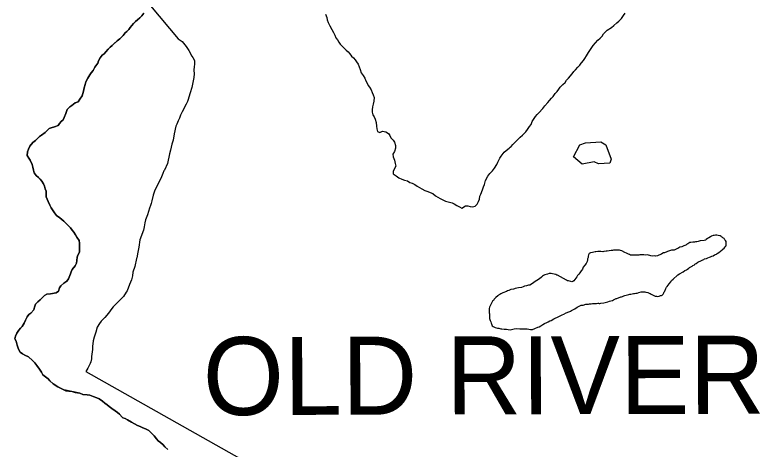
# Model space of a CAD drawing. Extents: x 3180038 to 3217926, y 922069 to 947485.
# Drawn here: x 3193100 to 3194055, y 938575 to 939132 of the extents above; entities that cross this region are included whole.
import ezdxf

# ---------------------------------------------------------------- set-up
doc = ezdxf.new("R2010")
doc.units = 0
for name, color, linetype in [('V-RIVR-IDEN', 7, 'Continuous'), ('V-SITE-VEGE', 7, 'Continuous'), ('V-TOPO-SHOR', 7, 'Continuous')]:
    doc.layers.add(name, color=color, linetype=linetype)

msp = doc.modelspace()

# ---------------------------------------------------------------- linework, layer by layer
at = {"layer": 'V-SITE-VEGE'}
for points in [[(3193273.3, 939143.31), (3193309.08, 939101.14), (3193314.24, 939097.64), (3193319.38, 939091.12), (3193322.8, 939086.33), (3193326.64, 939078.95), (3193327.92, 939077.21), (3193330.05, 939073.3), (3193330.01, 939068.11), (3193329.56, 939065.52), (3193329.09, 939060.77), (3193329.49, 939056.44), (3193329.02, 939051.68), (3193326.33, 939038.73), (3193324.11, 939031.83), (3193322.77, 939026.21), (3193321.88, 939023.19), (3193321, 939020.61), (3193319.24, 939017.16), (3193313.98, 939007.69), (3193311.78, 939003.38), (3193310.45, 938999.5), (3193309.13, 938996.04), (3193307.37, 938991.73), (3193306.05, 938989.15), (3193303.81, 938979.22), (3193302.45, 938971.44), (3193300.68, 938966.27), (3193298.89, 938958.5), (3193297.99, 938953.75), (3193295.3, 938941.22), (3193291.34, 938932.61), (3193290.47, 938931.75), (3193289.14, 938928.3), (3193286.5, 938922.26)], [(3193117.32, 938948.18), (3193115.35, 938951.62), (3193115.67, 938956.48), (3193116.84, 938959.9), (3193118.87, 938963.59), (3193122.34, 938968.13), (3193126.07, 938970.96), (3193128.66, 938973.23), (3193130.96, 938975.78), (3193133.84, 938977.76), (3193138.15, 938981.15), (3193140.74, 938983.71), (3193143.33, 938985.97), (3193146.19, 938987.09), (3193150.2, 938988.2), (3193155.07, 938990.16), (3193156.81, 938992.72), (3193158.83, 938995.28), (3193161.41, 938997.26), (3193162.58, 939000.1), (3193164.9, 939005.51), (3193166.37, 939010.36), (3193170.11, 939013.76), (3193172.41, 939015.74), (3193176.72, 939019.13), (3193180.73, 939020.53), (3193182.76, 939023.66), (3193185.65, 939027.92), (3193186.81, 939031.06), (3193187.41, 939034.19), (3193188.3, 939038.47), (3193189.47, 939042.75), (3193190.36, 939046.17), (3193192.96, 939050.72), (3193195.57, 939054.98), (3193197.3, 939057.54), (3193199.9, 939060.66), (3193202.21, 939064.93), (3193205.68, 939070.05), (3193206.85, 939072.89), (3193208.88, 939076.88), (3193211.47, 939080), (3193214.06, 939081.98), (3193216.08, 939084.53), (3193219.25, 939087.94), (3193221.55, 939090.49), (3193224.43, 939092.75), (3193227.88, 939096.15), (3193228.46, 939096.44), (3193230.76, 939098.7), (3193233.92, 939101.25), (3193236.22, 939103.23), (3193238.24, 939105.5), (3193240.83, 939108.62), (3193243.13, 939110.61), (3193245.44, 939113.16), (3193247.46, 939115.43), (3193249.48, 939117.98), (3193251.78, 939120.82), (3193254.37, 939123.37), (3193256.68, 939125.64), (3193259.84, 939128.19), (3193260.13, 939128.47), (3193262.43, 939130.74), (3193265.03, 939134.15)], [(3193214.88, 938634.33), (3193211.76, 938636.92), (3193207.78, 938639.53), (3193204.65, 938640.98), (3193199.8, 938642.73), (3193195.53, 938644.48), (3193192.11, 938645.07), (3193186.68, 938645.12), (3193182.69, 938646.86), (3193162.16, 938651.3), (3193158.18, 938653.34), (3193154.48, 938655.08), (3193148.51, 938658.84), (3193144.25, 938662.87), (3193142.27, 938665.46), (3193138.86, 938667.77), (3193135.46, 938670.65), (3193133.48, 938673.81), (3193131.23, 938677.83), (3193127.84, 938682.42), (3193125.01, 938685.87), (3193121.89, 938689.04), (3193116.78, 938693.36), (3193112.23, 938695.68), (3193109.1, 938697.42), (3193106.26, 938699.73), (3193104, 938703.46), (3193102.33, 938708.33), (3193100.94, 938713.77), (3193099.53, 938716.64), (3193100.13, 938720.06), (3193101.87, 938723.76), (3193104.76, 938727.74), (3193106.78, 938730.29), (3193108.8, 938732.56), (3193111.4, 938736.54), (3193113.14, 938740.53), (3193115.47, 938744.8), (3193117.2, 938747.64), (3193120.07, 938749.62), (3193123.82, 938753.87), (3193124.7, 938757.29), (3193126.16, 938761), (3193129.04, 938763.83), (3193131.92, 938766.66), (3193134.8, 938769.5), (3193137.67, 938772.33), (3193140.54, 938774.03), (3193145.12, 938774.27), (3193152.27, 938775.65), (3193155.43, 938777.62), (3193156.89, 938781.9), (3193158.34, 938784.74), (3193162.08, 938788.14), (3193166.1, 938790.68), (3193168.12, 938793.52), (3193170.74, 938799.79), (3193171.9, 938802.63), (3193173.07, 938805.48), (3193176.82, 938810.02), (3193178.56, 938813.72), (3193179.16, 938817.15), (3193179.19, 938821.15), (3193180.35, 938823.99), (3193182.38, 938827.69), (3193182.41, 938830.83), (3193182.44, 938835.41), (3193182.47, 938839.12), (3193181.93, 938842.84), (3193178.82, 938846.86), (3193177.12, 938849.73), (3193175.15, 938853.17), (3193173.17, 938856.05), (3193170.91, 938858.92), (3193167.79, 938862.08), (3193164.96, 938864.68), (3193162.12, 938867.27), (3193157.3, 938871.59), (3193153.04, 938874.77), (3193150.2, 938877.93), (3193148.8, 938880.8), (3193146.25, 938884.54), (3193144.28, 938887.98), (3193142.32, 938892.56), (3193140.91, 938895.72), (3193139.51, 938898.58), (3193139.54, 938902.58), (3193139.57, 938906.01), (3193138.45, 938908.88), (3193137.33, 938912.31), (3193136.21, 938915.46), (3193134.24, 938918.62), (3193131.97, 938921.21), (3193129.7, 938923.23), (3193126.87, 938926.11), (3193124.32, 938929.55), (3193123.2, 938932.99), (3193122.66, 938936.42), (3193121.83, 938939.86), (3193119.02, 938945.59), (3193117.32, 938948.18)], [(3193286.5, 938922.26), (3193279.03, 938907.18), (3193276.82, 938900.71), (3193275.03, 938893.37), (3193274.14, 938889.92), (3193273.26, 938887.33), (3193272.36, 938883.88), (3193269.7, 938875.68), (3193267.06, 938869.22), (3193266.17, 938865.33), (3193265.26, 938860.15), (3193264.36, 938855.83), (3193259.94, 938843.32), (3193258.57, 938834.25), (3193257.22, 938827.77), (3193255.87, 938820.43), (3193255.43, 938819.57), (3193253.19, 938809.21), (3193250.97, 938801.87), (3193250.5, 938797.55), (3193249.16, 938792.37), (3193246.52, 938786.33), (3193243.43, 938778.14), (3193242.12, 938776.42), (3193238.62, 938770.83), (3193235.56, 938767.39), (3193225.54, 938757.52), (3193223.79, 938755.37), (3193219.42, 938749.35), (3193215.05, 938743.76), (3193210.26, 938739.47), (3193208.08, 938736.46), (3193205.01, 938731.73), (3193203.23, 938725.25), (3193201.02, 938718.78), (3193200.12, 938714.03), (3193199.2, 938706.69), (3193199.17, 938702.8), (3193197.8, 938694.16), (3193197.78, 938691.13), (3193196.88, 938687.24), (3193196, 938685.09), (3193192.93, 938679.06), (3193190.3, 938674.75), (3193761.24, 938352.95)], [(3193295.83, 938574.86), (3193291.86, 938578.31), (3193289.59, 938580.62), (3193286.19, 938583.79), (3193283.35, 938586.09), (3193281.09, 938588.68), (3193278.26, 938592.13), (3193275.42, 938595.01), (3193271.45, 938599.04), (3193267.19, 938601.36), (3193263.77, 938602.53), (3193260.07, 938604.27), (3193256.65, 938605.72), (3193252.95, 938607.75), (3193249.25, 938609.78), (3193243.85, 938612.97), (3193241.01, 938614.42), (3193238.16, 938615.58), (3193237.31, 938616.44), (3193233.62, 938620.19), (3193231.07, 938622.2), (3193228.23, 938624.23), (3193223.68, 938627.4), (3193220.27, 938630), (3193218, 938632.02), (3193214.88, 938634.33)]]:
    msp.add_lwpolyline(points, dxfattribs=at)
at = {"layer": 'V-TOPO-SHOR'}
for points in [[(3193265.03, 939134.15), (3193262.43, 939130.74), (3193260.13, 939128.47), (3193259.84, 939128.19), (3193256.68, 939125.64), (3193254.37, 939123.37), (3193251.78, 939120.82), (3193249.48, 939117.98), (3193247.45, 939115.43), (3193245.44, 939113.16), (3193243.13, 939110.61), (3193240.83, 939108.62), (3193238.24, 939105.5), (3193236.22, 939103.23), (3193233.92, 939101.25), (3193230.76, 939098.7), (3193228.46, 939096.44), (3193227.88, 939096.15), (3193224.43, 939092.75), (3193221.55, 939090.49), (3193219.25, 939087.94), (3193216.08, 939084.53), (3193214.06, 939081.98), (3193211.47, 939080), (3193208.88, 939076.88), (3193206.85, 939072.89), (3193205.68, 939070.05), (3193202.21, 939064.93), (3193199.9, 939060.66), (3193197.3, 939057.54), (3193195.57, 939054.98), (3193192.96, 939050.72), (3193190.36, 939046.17), (3193189.47, 939042.75), (3193188.3, 939038.47), (3193187.41, 939034.19), (3193186.81, 939031.06), (3193185.65, 939027.92), (3193182.76, 939023.66), (3193180.73, 939020.53), (3193176.72, 939019.13), (3193172.41, 939015.74), (3193170.11, 939013.76), (3193166.37, 939010.36), (3193164.9, 939005.51), (3193162.58, 939000.1), (3193161.41, 938997.26), (3193158.83, 938995.28), (3193156.81, 938992.72), (3193155.07, 938990.16), (3193150.2, 938988.2), (3193146.19, 938987.09), (3193143.33, 938985.97), (3193140.74, 938983.71), (3193138.15, 938981.15), (3193133.84, 938977.76), (3193130.96, 938975.78), (3193128.66, 938973.23), (3193126.07, 938970.96), (3193122.34, 938968.13), (3193118.87, 938963.59), (3193116.84, 938959.89), (3193115.67, 938956.48), (3193115.35, 938951.62), (3193117.32, 938948.18), (3193119.02, 938945.59), (3193121.83, 938939.86), (3193122.66, 938936.42), (3193123.2, 938932.99), (3193124.32, 938929.55), (3193126.87, 938926.11), (3193129.7, 938923.23), (3193131.97, 938921.21)], [(3193498.03, 939132.85), (3193499.42, 939128.55), (3193499.97, 939125.41), (3193501.37, 939121.97), (3193503.34, 939117.95), (3193505.88, 939113.08), (3193508.13, 939109.06), (3193509.82, 939105.62), (3193511.22, 939102.18), (3193513.2, 939099.88), (3193514.89, 939096.72), (3193516.87, 939094.14), (3193519.42, 939091.83), (3193521.97, 939088.96), (3193524.52, 939086.65), (3193526.79, 939084.35), (3193529.06, 939081.76), (3193531.32, 939078.89), (3193533.87, 939076.58), (3193535.85, 939073.99), (3193537.83, 939071.41), (3193539.81, 939068.54), (3193540.93, 939065.38), (3193542.33, 939061.95), (3193543.73, 939057.65), (3193546.27, 939054.2), (3193548.24, 939050.76), (3193549.65, 939047.32), (3193551.33, 939044.16), (3193552.46, 939041.3), (3193554.44, 939039), (3193556.41, 939035.55), (3193557.81, 939032.12), (3193559.22, 939029.25), (3193560.34, 939026.1), (3193560.01, 939021.24), (3193558.84, 939017.54), (3193558.24, 939014.12), (3193557.64, 939010.12), (3193557.62, 939006.98), (3193558.73, 939003.54), (3193560.43, 939000.96), (3193561.55, 938998.09), (3193562.66, 938993.8), (3193563.48, 938989.22), (3193563.74, 938985.79), (3193564.57, 938982.36), (3193567.7, 938981.19), (3193570.86, 938982.88), (3193575.13, 938981.7), (3193578.55, 938979.96), (3193578.83, 938979.68), (3193580.24, 938977.09), (3193581.65, 938974.23), (3193584.48, 938971.35), (3193586.17, 938968.48), (3193587.57, 938964.47), (3193587.83, 938961.04), (3193586.37, 938956.76), (3193584.34, 938953.35), (3193584.6, 938949.92), (3193586.28, 938945.62), (3193587.39, 938941.33), (3193587.93, 938937.9), (3193585.91, 938933.91), (3193584.74, 938931.07), (3193584.72, 938927.92), (3193588.69, 938925.32), (3193592.1, 938923.01), (3193595.81, 938921.27), (3193599.22, 938920.1), (3193602.93, 938918.93)], [(3193602.93, 938918.93), (3193606.06, 938917.19), (3193608.9, 938916.03), (3193612.32, 938914.28), (3193615.45, 938912.26), (3193621.42, 938908.79), (3193625.12, 938906.76), (3193629.1, 938905.3), (3193632.24, 938904.13), (3193635.37, 938902.68), (3193639.06, 938900.08), (3193641.9, 938898.06), (3193645.03, 938896.32), (3193649.02, 938894.29), (3193651.86, 938893.12), (3193656.71, 938891.66), (3193660.13, 938890.78), (3193662.98, 938889.61), (3193666.39, 938887.58), (3193669.81, 938885.84), (3193672.93, 938884.11), (3193677.24, 938887.21), (3193680.39, 938887.19), (3193683.23, 938886.03), (3193686.37, 938885.71), (3193689.81, 938886.83), (3193692.4, 938889.38), (3193694.14, 938892.8), (3193695.59, 938895.64), (3193695.91, 938899.35), (3193697.07, 938902.2), (3193699.11, 938907.61), (3193700.57, 938911.6), (3193701.74, 938914.45), (3193703.2, 938919.58), (3193706.1, 938924.99), (3193708.7, 938928.68), (3193712.16, 938932.08), (3193714.47, 938935.2), (3193717.64, 938940.04), (3193718.81, 938943.17), (3193721.42, 938948), (3193723.15, 938950.56), (3193727.19, 938955.96), (3193729.5, 938957.94), (3193733.23, 938960.77), (3193734.67, 938962.47), (3193735.82, 938963.03), (3193738.12, 938965.59), (3193743.02, 938970.41), (3193745.04, 938972.68), (3193747.63, 938975.23), (3193750.5, 938977.78), (3193754.82, 938982.03), (3193757.13, 938984.87), (3193759.73, 938988.56), (3193761.46, 938991.12), (3193762.92, 938995.1), (3193767.26, 939001.64), (3193769.28, 939004.2), (3193771.58, 939006.46), (3193776.48, 939011.86), (3193779.07, 939015.26), (3193783.11, 939019.52), (3193785.13, 939022.07), (3193787.72, 939024.91), (3193790.02, 939027.18), (3193792.62, 939031.16), (3193794.93, 939033.71), (3193797.24, 939036.55), (3193798.97, 939039.11), (3193802.14, 939042.51), (3193805.3, 939045.34), (3193807.04, 939048.18), (3193809.34, 939050.74), (3193814.24, 939056.41), (3193816.55, 939059.25), (3193818.57, 939061.52), (3193821.45, 939064.64), (3193824.04, 939067.48), (3193825.78, 939070.03), (3193826.06, 939070.32), (3193828.94, 939073.15), (3193830.39, 939076), (3193832.42, 939079.41), (3193835.02, 939083.39), (3193837.62, 939087.37), (3193839.36, 939089.93), (3193841.38, 939092.48), (3193844.26, 939095.89), (3193847.14, 939099.29), (3193850.31, 939102.13), (3193852.61, 939104.68), (3193854.64, 939107.52), (3193856.65, 939109.79), (3193859.24, 939112.06), (3193864.69, 939115.44), (3193867.86, 939117.99), (3193871.59, 939121.39), (3193874.18, 939123.65), (3193877.64, 939127.05)], [(3193877.64, 939127.05), (3193880.24, 939131.03), (3193882.27, 939134.16)], [(3193831.14, 938967.89), (3193851.01, 938968.91), (3193857.27, 938965.08), (3193864.23, 938946.78), (3193862.66, 938941.58), (3193848, 938940.71), (3193842.63, 938943.45), (3193827.15, 938940.61), (3193815.99, 938950.04), (3193824.2, 938965.25), (3193831.14, 938967.89)], [(3193131.97, 938921.21), (3193134.24, 938918.62), (3193136.21, 938915.46), (3193137.33, 938912.31), (3193138.45, 938908.88), (3193139.57, 938906.01), (3193139.54, 938902.58), (3193139.51, 938898.58), (3193140.91, 938895.72), (3193142.32, 938892.56), (3193144.28, 938887.98), (3193146.25, 938884.54), (3193148.8, 938880.8), (3193150.2, 938877.93), (3193153.04, 938874.77), (3193157.3, 938871.59), (3193162.12, 938867.27), (3193164.96, 938864.68), (3193167.79, 938862.08), (3193170.91, 938858.92), (3193173.17, 938856.05), (3193175.15, 938853.17), (3193177.12, 938849.73), (3193178.82, 938846.86), (3193181.93, 938842.84), (3193182.47, 938839.12), (3193182.44, 938835.41), (3193182.41, 938830.83), (3193182.38, 938827.69), (3193180.35, 938823.99), (3193179.19, 938821.15), (3193179.16, 938817.15), (3193178.56, 938813.72), (3193176.82, 938810.02), (3193173.07, 938805.48), (3193171.9, 938802.63), (3193170.74, 938799.79), (3193168.12, 938793.52), (3193166.1, 938790.68), (3193162.08, 938788.14), (3193158.34, 938784.74), (3193156.89, 938781.9), (3193155.43, 938777.62), (3193152.27, 938775.65), (3193145.12, 938774.27), (3193140.54, 938774.03), (3193137.67, 938772.33), (3193134.8, 938769.5), (3193131.92, 938766.66), (3193129.04, 938763.83), (3193126.16, 938761), (3193124.7, 938757.29), (3193123.82, 938753.87), (3193120.07, 938749.62), (3193117.2, 938747.64), (3193115.47, 938744.8), (3193113.14, 938740.53), (3193111.4, 938736.54), (3193108.8, 938732.56), (3193106.78, 938730.29), (3193104.76, 938727.74), (3193101.87, 938723.76), (3193100.13, 938720.06), (3193099.53, 938716.64), (3193100.94, 938713.77), (3193102.33, 938708.33), (3193104, 938703.46), (3193106.26, 938699.73), (3193109.1, 938697.42), (3193112.23, 938695.68), (3193116.78, 938693.36), (3193121.89, 938689.04), (3193125.01, 938685.87), (3193127.84, 938682.42), (3193131.23, 938677.83), (3193133.48, 938673.81), (3193135.46, 938670.65), (3193138.86, 938667.77), (3193142.27, 938665.46), (3193144.25, 938662.87), (3193148.51, 938658.84), (3193154.48, 938655.08), (3193158.18, 938653.34), (3193162.16, 938651.3), (3193165.01, 938649.85), (3193168.72, 938649.54), (3193173, 938648.94), (3193176.7, 938647.77), (3193182.69, 938646.86), (3193186.68, 938645.12), (3193192.11, 938645.07), (3193195.53, 938644.48), (3193199.8, 938642.73), (3193204.65, 938640.98), (3193207.78, 938639.53), (3193211.76, 938636.92), (3193214.88, 938634.33), (3193218, 938632.02), (3193220.27, 938630), (3193223.68, 938627.4), (3193228.23, 938624.23)], [(3193980.03, 938816.97), (3193981.75, 938817.82), (3193983.18, 938818.38), (3193984.04, 938818.94), (3193986.34, 938819.78), (3193988.06, 938820.63), (3193990.35, 938821.46), (3193991.5, 938821.74), (3193993.22, 938822.59), (3193994.93, 938823.14), (3193996.94, 938824.27), (3193998.09, 938824.55), (3193999.23, 938825.11), (3194000.38, 938825.96), (3194002.39, 938827.08), (3194004.4, 938828.78), (3194006.7, 938830.48), (3194007.57, 938831.33), (3194009.01, 938833.03), (3194010.45, 938834.45), (3194011.31, 938835.59), (3194011.61, 938836.73), (3194011.62, 938837.87), (3194011.91, 938839.29), (3194011.64, 938841.3), (3194011.08, 938842.44), (3194010.23, 938843.59), (3194009.67, 938844.45), (3194009.39, 938845.03), (3194007.68, 938846.18), (3194006.83, 938847.05), (3194005.69, 938847.34), (3194005.41, 938847.63), (3194003.99, 938848.5), (3194001.7, 938849.09), (3193999.71, 938849.39), (3193997.99, 938849.4), (3193996.28, 938849.13), (3193995.13, 938848.85), (3193992.84, 938848.01), (3193991.69, 938847.45), (3193989.68, 938846.04), (3193987.68, 938845.2), (3193986.24, 938843.78), (3193985.09, 938843.22), (3193983.37, 938842.66), (3193978.51, 938842.13), (3193975.94, 938841.57), (3193973.93, 938841.02), (3193972.5, 938840.74), (3193971.07, 938840.47), (3193969.07, 938840.48), (3193966.5, 938840.22), (3193965.35, 938839.94), (3193963.92, 938839.38), (3193962.77, 938838.53), (3193961.05, 938837.69), (3193959.9, 938836.84), (3193957.61, 938836), (3193955.03, 938834.59), (3193952.45, 938834.04), (3193951.02, 938833.2), (3193949.58, 938832.35), (3193948.44, 938832.07), (3193945, 938830.39), (3193943.57, 938830.11), (3193941.85, 938830.12), (3193940.42, 938829.85), (3193938.99, 938829.29), (3193936.7, 938828.74), (3193935.84, 938828.17), (3193932.68, 938826.77), (3193931.54, 938826.78), (3193929.25, 938825.37), (3193927.81, 938824.81), (3193925.23, 938823.68), (3193923.8, 938823.12), (3193921.51, 938822.57), (3193920.09, 938822.87), (3193917.23, 938822.6), (3193915.23, 938822.9), (3193910.95, 938824.08), (3193907.81, 938823.82), (3193906.1, 938824.12), (3193902.67, 938824.14), (3193901.24, 938824.15), (3193899.81, 938823.88), (3193898.67, 938823.89), (3193896.1, 938823.91), (3193892.95, 938823.65), (3193891.81, 938823.66), (3193890.38, 938823.67), (3193889.24, 938823.96), (3193887.82, 938824.54), (3193886.39, 938825.12), (3193884.97, 938825.99), (3193883.83, 938826.29), (3193881.84, 938827.45), (3193878.14, 938829.19), (3193876.15, 938829.78), (3193875.01, 938830.07)], [(3193875.01, 938830.07), (3193873.58, 938830.37), (3193868.72, 938830.4), (3193867.29, 938830.13), (3193865.86, 938829.86), (3193864.15, 938829.87), (3193861.57, 938829.32), (3193859, 938828.77), (3193857.85, 938828.77), (3193855, 938828.51), (3193853.57, 938828.24), (3193851, 938828.54), (3193847, 938828.57), (3193844.71, 938828.31), (3193843.57, 938828.03), (3193842.14, 938827.75), (3193840.13, 938827.48), (3193837.56, 938826.93), (3193836.12, 938826.09), (3193835.55, 938825.23), (3193835.25, 938824.09), (3193834.67, 938822.67), (3193834.65, 938820.67), (3193834.07, 938818.96), (3193834.06, 938817.82), (3193833.47, 938815.54), (3193832.31, 938813.26), (3193830.58, 938810.99), (3193828.56, 938808.43), (3193827.98, 938807.29), (3193827.4, 938805.87), (3193826.53, 938804.73), (3193825.95, 938803.6), (3193824.22, 938801.04), (3193822.78, 938799.34), (3193821.91, 938798.49), (3193821.05, 938797.64), (3193820.18, 938796.22), (3193819.02, 938794.22), (3193817.87, 938792.81), (3193816.43, 938791.1), (3193814.99, 938790.26), (3193813.85, 938789.69), (3193812.7, 938789.99), (3193809.57, 938790.87), (3193808.43, 938790.88), (3193807.01, 938791.75), (3193795.63, 938798.12)], [(3193798.65, 938746.1), (3193801.23, 938747.23), (3193803.53, 938748.35), (3193806.39, 938749.76), (3193809.84, 938751.16), (3193811.27, 938751.72), (3193812.13, 938752.28), (3193813.28, 938752.85), (3193815, 938753.69), (3193817.58, 938755.1), (3193820.73, 938757.07), (3193823.03, 938758.48), (3193824.18, 938759.05), (3193825.61, 938759.61), (3193826.75, 938759.6), (3193828.18, 938759.87), (3193831.62, 938760.99), (3193833.05, 938761.26), (3193835.34, 938761.25), (3193836.48, 938761.52), (3193838.77, 938761.5), (3193840.2, 938761.78), (3193841.34, 938761.77), (3193843.34, 938761.76), (3193845.63, 938762.02), (3193847.34, 938762.3), (3193847.91, 938762.29), (3193848.77, 938762), (3193849.91, 938761.7), (3193851.06, 938762.27), (3193855.06, 938762.81), (3193856.49, 938763.08), (3193859.93, 938764.2), (3193861.93, 938764.75), (3193863.94, 938765.31), (3193865.94, 938765.87), (3193867.37, 938766.71), (3193868.81, 938767.56), (3193870.53, 938768.11), (3193871.67, 938768.39), (3193876.54, 938770.35), (3193877.69, 938770.63), (3193878.83, 938770.91), (3193880.55, 938771.75), (3193881.99, 938772.31), (3193885.14, 938773.14), (3193886.85, 938773.42), (3193888, 938773.69), (3193889.42, 938773.68), (3193891.14, 938774.24), (3193892.86, 938774.8), (3193894.29, 938774.79), (3193896.01, 938775.35), (3193897.43, 938775.33), (3193899.73, 938775.89), (3193902.59, 938776.72), (3193907.45, 938776.69), (3193908.87, 938776.39), (3193911.15, 938775.8), (3193912.86, 938775.21), (3193914.29, 938774.63), (3193915.71, 938773.76), (3193917.41, 938773.18), (3193918.84, 938772.31), (3193919.97, 938771.73), (3193920.83, 938771.15), (3193922.26, 938771.14), (3193923.4, 938770.85), (3193925.68, 938771.12), (3193927.69, 938771.96), (3193928.83, 938772.24), (3193929.7, 938772.8), (3193930.85, 938773.93), (3193931.43, 938774.78), (3193932, 938775.64), (3193932.3, 938777.06), (3193932.88, 938777.92), (3193934.33, 938781.05), (3193935.2, 938783.04), (3193936.07, 938783.61), (3193938.66, 938787.01), (3193940.68, 938789.85), (3193941.84, 938791.27), (3193943.57, 938793.26), (3193944.43, 938794.11), (3193948.46, 938797.51), (3193949.61, 938798.64), (3193951.9, 938799.77), (3193956.78, 938802.58), (3193958.79, 938804), (3193960.8, 938805.12), (3193961.95, 938805.97), (3193963.67, 938807.1), (3193964.82, 938807.95), (3193967.98, 938809.64), (3193968.84, 938810.49), (3193971.13, 938811.61), (3193971.71, 938812.47), (3193973.15, 938813.31), (3193975.44, 938814.72), (3193980.03, 938816.97)], [(3193795.63, 938798.12), (3193795.63, 938798.12), (3193794.49, 938798.41), (3193793.35, 938798.99), (3193791.35, 938799.3), (3193789.07, 938799.88), (3193787.36, 938800.18), (3193786.22, 938800.19), (3193784.79, 938800.2), (3193782.79, 938799.65), (3193779.06, 938798.53), (3193777.34, 938797.69), (3193776.19, 938796.84), (3193775.04, 938795.71), (3193772.17, 938793.44), (3193768.72, 938791.19), (3193766.71, 938790.06), (3193764.99, 938788.64), (3193762.12, 938786.67), (3193759.82, 938785.54), (3193758.39, 938785.27), (3193755.82, 938784.71), (3193752.96, 938784.16), (3193751.52, 938783.32), (3193749.23, 938782.48), (3193745.23, 938781.94), (3193743.22, 938781.67), (3193741.22, 938781.12), (3193740.07, 938780.84), (3193738.93, 938780.27), (3193735.5, 938779.73), (3193732.91, 938778.61), (3193731.48, 938778.05), (3193730.05, 938777.2), (3193728.9, 938776.93), (3193726.61, 938775.8), (3193725.18, 938775.52), (3193722.6, 938774.12), (3193721.45, 938773.27), (3193719.73, 938772.42), (3193718.87, 938771.86), (3193716.28, 938769.6), (3193714.26, 938767.32), (3193713.39, 938765.9), (3193712.24, 938764.77), (3193711.08, 938763.06), (3193709.63, 938759.65), (3193708.76, 938757.94), (3193708.18, 938757.09), (3193707.88, 938755.38), (3193707.87, 938753.95), (3193707.86, 938751.95), (3193707.84, 938749.95), (3193708.12, 938748.52), (3193708.38, 938746.23), (3193708.08, 938743.66), (3193708.07, 938742.52), (3193708.63, 938741.37), (3193708.91, 938740.23), (3193709.75, 938738.51), (3193710.31, 938736.79), (3193710.87, 938735.64), (3193711.71, 938733.35), (3193713.13, 938732.48), (3193715.7, 938731.32), (3193718.55, 938730.44), (3193720.26, 938730.14), (3193721.4, 938729.85), (3193722.82, 938729.55), (3193723.97, 938729.54), (3193726.82, 938728.95), (3193729.96, 938728.92), (3193732.24, 938728.62), (3193734.81, 938728.31), (3193737.96, 938728.86), (3193739.96, 938729.42), (3193743.39, 938729.96), (3193747.11, 938729.65), (3193748.82, 938729.35), (3193751.68, 938729.61), (3193753.68, 938729.6), (3193756.53, 938729.29), (3193758.53, 938728.99), (3193760.81, 938728.69), (3193763.38, 938728.67), (3193766.25, 938729.79), (3193770.26, 938731.47), (3193771.98, 938732.03), (3193773.99, 938733.44), (3193775.14, 938734), (3193776.57, 938734.85), (3193778.87, 938736.26), (3193781.73, 938737.66), (3193783.46, 938738.51), (3193785.46, 938739.64), (3193787.18, 938740.19), (3193790.91, 938742.16), (3193792.35, 938743.01), (3193793.21, 938743.58), (3193794.64, 938744.13), (3193798.65, 938746.1)], [(3193228.23, 938624.23), (3193231.07, 938622.2), (3193233.62, 938620.19), (3193237.31, 938616.44), (3193238.16, 938615.58), (3193241.01, 938614.42), (3193243.85, 938612.97), (3193249.25, 938609.78), (3193252.95, 938607.75), (3193256.65, 938605.72), (3193260.07, 938604.27), (3193263.77, 938602.53), (3193267.19, 938601.36), (3193271.45, 938599.04), (3193275.42, 938595.01), (3193278.26, 938592.13), (3193281.09, 938588.68), (3193283.35, 938586.09), (3193286.19, 938583.79), (3193289.59, 938580.62), (3193291.86, 938578.31), (3193295.83, 938574.86)]]:
    msp.add_lwpolyline(points, dxfattribs=at)

# ---------------------------------------------------------------- texts
at = {"layer": 'V-RIVR-IDEN'}
msp.add_text('OLD RIVER', height=100, rotation=0.14529, dxfattribs=at).set_placement((3193340.69, 938618.86))

doc.saveas('drawing.dxf')
